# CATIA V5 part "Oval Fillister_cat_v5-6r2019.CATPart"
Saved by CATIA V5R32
Part number: Oval Fillister
Bounding box of the stored display mesh (mm): x -5 to 5, y -5 to 5, z -7 to 4
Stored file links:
  D:\PROJECTS\Project 2022\CATIA V5 6R 2022\Resources\Tutorial Files\c16_catia_v5_6r2022_tut\Bench vice\Oval Fillister_cat_v5-6r2019.CATPart
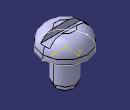
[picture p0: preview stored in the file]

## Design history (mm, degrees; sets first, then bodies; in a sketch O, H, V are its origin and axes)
Body1 (main body)
  Sketch1 on xy-plane, origin (0, 0, 0), H (1, 0, 0), V (0, 1, 0)
    circle A1 centre (0, 0) radius 5
    radius A1 = 5
  Pad1: profile Sketch1, direction (0, 0, 1), length 4
  Sketch2 on face of Pad1, origin (0, 0, 0), H (1, 0, 0), V (0, -1, 0)
    circle A1 centre (0, 0) radius 2.5
    radius A1 = 2.5
  Pad2: profile Sketch2, direction (0, 0, -1), length 6
  Sketch3 on face of Pad2, origin (0, 0, -6), H (1, 0, 0), V (0, -1, 0)
    circle A1 centre (0, 0) radius 2
    radius A1 = 2
  Pad3: profile Sketch3, direction (0, 0, -1), length 1
  Fillet1: radius 3, on 1 edge
  Sketch4 on yz-plane, origin (0, 0, 0), H (0, 1, 0), V (0, 0, 1)
    line L1 (-1, 4.5549) -> (1, 4.5549)
    line L2 (1, 4.5549) -> (1, 2.5)
    line L3 (1, 2.5) -> (-1, 2.5)
    line L4 (-1, 2.5) -> (-1, 4.5549)
    distance H L3 = 2.5
    distance L2 V = 1
    length L1 = 2
    horizontal: L1 H, L3 H
    vertical: L2 V, L4 V
  Pocket1: profile Sketch4, direction (-1, 0, 0), length 8, mirrored extent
